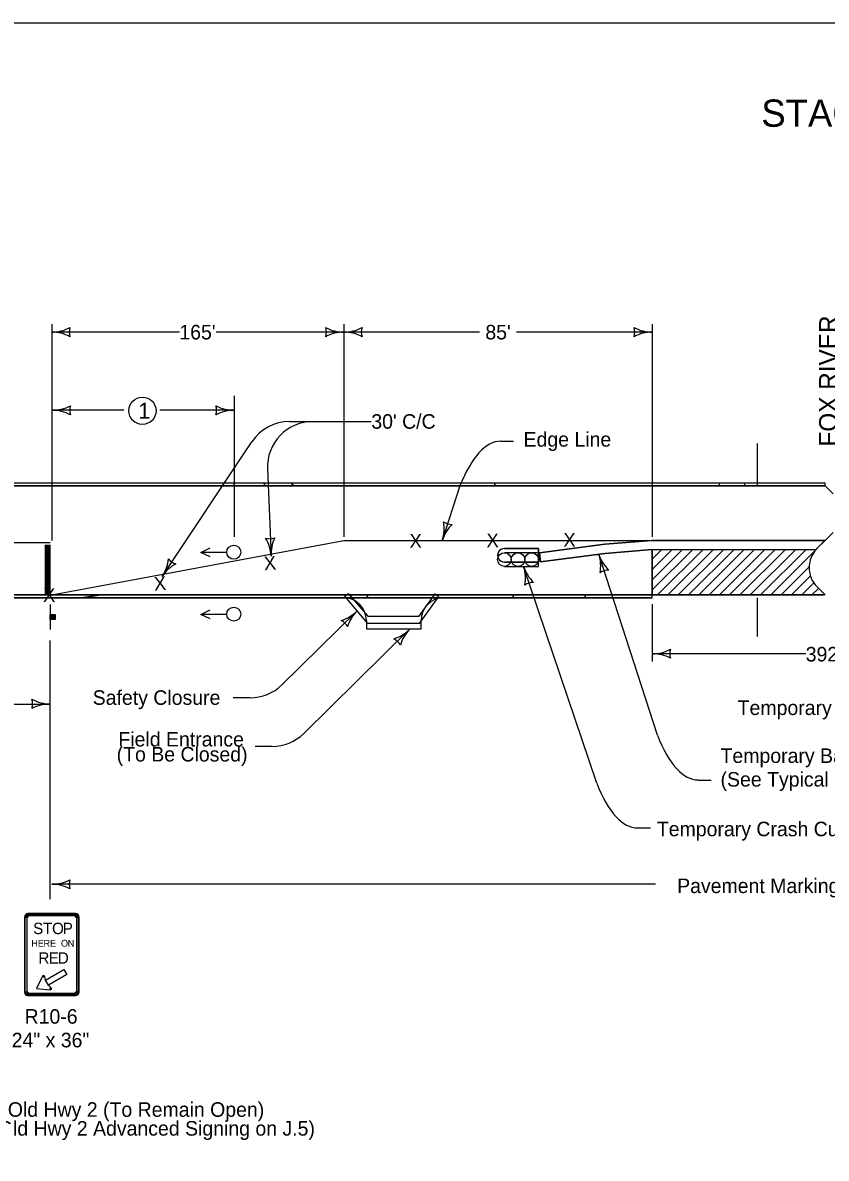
# Model space of a CAD drawing. Extents: x -2134934 to -2119606, y -2139046 to -2137036.
# Drawn here: x -2129562 to -2128679, y -2138285 to -2137036 of the extents above; entities that cross this region are included whole.
import ezdxf

# ---------------------------------------------------------------- set-up
doc = ezdxf.new("R2010")
doc.units = 0
for name, color, linetype in [('Default', 7, 'Continuous'), ('dsnCellElements', 7, 'Continuous'), ('dsnCellsNorthArrow', 7, 'Continuous'), ('dsnStdLabel', 7, 'Continuous'), ('dsnStdLineWork', 7, 'Continuous'), ('dsnStdShading', 7, 'Continuous'), ('Level 2', 7, 'Continuous')]:
    doc.layers.add(name, color=color, linetype=linetype)

msp = doc.modelspace()

# ---------------------------------------------------------------- linework, layer by layer
at = {"layer": 'Default'}
for p, q in [((-2129208, -2137666.4), (-2129204.2, -2137663.4)), ((-2129204.2, -2137663.4), (-2129182.8, -2137688.4)), ((-2129126.3, -2137688.4), (-2129108.6, -2137664.1)), ((-2129108.6, -2137664.1), (-2129105.1, -2137666.7)), ((-2129182.8, -2137696.5), (-2129208, -2137666.4)), ((-2129105.1, -2137666.7), (-2129126.3, -2137696.5)), ((-2129182.8, -2137688.4), (-2129126.3, -2137688.4)), ((-2129126.3, -2137696.5), (-2129182.8, -2137696.5))]:
    msp.add_line(p, q, dxfattribs=at)
msp.add_lwpolyline([(-2130232, -2137035.9), (-2127097, -2137035.9), (-2127097, -2139045.9), (-2130232, -2139045.9)], close=True, dxfattribs=at)
at = {"layer": 'dsnCellElements'}
for centre, radius, start, end in [((-2129530.1, -2137333.7), 42.5, 270, 298.0725), ((-2129530.1, -2137418.7), 42.5, 61.9275, 90), ((-2129494.5, -2137376.2), 16.4, 162.2666, 197.7334), ((-2129244.7, -2137376.2), 16.4, 342.2666, 17.7334), ((-2129209.1, -2137333.7), 42.5, 241.9275, 270), ((-2129209.1, -2137418.7), 42.5, 90, 118.0725), ((-2129209.1, -2137333.7), 42.5, 270, 298.0725), ((-2129209.1, -2137418.7), 42.5, 61.9275, 90), ((-2129173.5, -2137376.2), 16.4, 162.2666, 197.7334), ((-2128905.8, -2137376.2), 16.4, 342.2666, 17.7334), ((-2128870.1, -2137333.7), 42.5, 241.9275, 270), ((-2128870.1, -2137418.7), 42.5, 90, 118.0725), ((-2129141.4, -2137592.1), 42.5, 342.0849, 10.1574), ((-2129060.5, -2137618.2), 42.5, 134.0124, 162.0849), ((-2129090, -2137571.3), 16.4, 234.3516, 269.8183), ((-2129290.8, -2137586.9), 16.4, 255.0909, 290.5576), ((-2129331.5, -2137624.5), 42.5, 2.8243, 30.8968), ((-2129246.6, -2137620.4), 42.5, 154.7518, 182.8243), ((-2129444.2, -2137621.2), 42.5, 326.2987, 354.3712), ((-2129389.1, -2137615.2), 16.4, 218.5654, 254.0321), ((-2128969.3, -2137633.4), 42.5, 349.8426, 17.9151), ((-2128888.4, -2137607.3), 42.5, 197.9151, 225.9876), ((-2129373.5, -2137668.4), 42.5, 118.2263, 146.2987), ((-2129051.9, -2137646.9), 42.5, 349.8426, 17.9151), ((-2128971, -2137620.8), 42.5, 197.9151, 225.9876), ((-2128917.9, -2137654.2), 16.4, 90.1817, 125.6484), ((-2129000.5, -2137667.7), 16.4, 90.1817, 125.6484), ((-2129224.6, -2137652.6), 42.5, 287.1972, 315.2696), ((-2129164.3, -2137712.4), 42.5, 135.2696, 163.3421), ((-2129219.5, -2137707.8), 16.4, 27.5363, 63.003), ((-2129166.7, -2137672.7), 42.5, 287.1972, 315.2696), ((-2129106.3, -2137732.6), 42.5, 135.2696, 163.3421), ((-2129161.6, -2137728), 16.4, 27.5363, 63.003), ((-2129530.1, -2137940.8), 42.5, 270, 298.0725), ((-2129530.1, -2138025.8), 42.5, 61.9275, 90), ((-2129494.5, -2137983.3), 16.4, 162.2666, 197.7334)]:
    msp.add_arc(centre, radius, start, end, dxfattribs=at)
at = {"layer": 'dsnStdLabel'}
for p, q in [((-2129560.1, -2138019.4), (-2129556.4, -2138019.4)), ((-2129559.2, -2138019.4), (-2129557.6, -2138019.4)), ((-2129556.4, -2138019.4), (-2129556.4, -2138015.6)), ((-2129556.4, -2138018.1), (-2129556.4, -2138016.6)), ((-2129503.9, -2138015.6), (-2129503.9, -2138019.4)), ((-2129503.9, -2138016.6), (-2129503.9, -2138018.1)), ((-2129503.9, -2138019.4), (-2129500.1, -2138019.4)), ((-2129502.6, -2138019.4), (-2129501.1, -2138019.4)), ((-2129540.3, -2138084.4), (-2129539.2, -2138085)), ((-2129539.2, -2138085), (-2129537.9, -2138084.7)), ((-2129556.4, -2138101.9), (-2129560.1, -2138101.9)), ((-2129557.6, -2138101.9), (-2129559.2, -2138101.9)), ((-2129556.4, -2138105.6), (-2129556.4, -2138101.9)), ((-2129530.8, -2138097), (-2129531.7, -2138098)), ((-2129531.7, -2138098), (-2129531.7, -2138099.2)), ((-2129500.1, -2138101.9), (-2129503.9, -2138101.9)), ((-2129503.9, -2138101.9), (-2129503.9, -2138105.6)), ((-2129501.1, -2138101.9), (-2129502.6, -2138101.9)), ((-2129556.4, -2138104.7), (-2129556.4, -2138103.1)), ((-2129503.9, -2138103.1), (-2129503.9, -2138104.7))]:
    msp.add_line(p, q, dxfattribs=at)
for points in [[(-2129556.4, -2138105.6), (-2129503.9, -2138105.6), (-2129503.9, -2138101.9), (-2129500.1, -2138101.9), (-2129500.1, -2138019.4), (-2129503.9, -2138019.4), (-2129503.9, -2138015.6), (-2129556.4, -2138015.6), (-2129556.4, -2138019.4), (-2129560.1, -2138019.4), (-2129560.1, -2138101.9), (-2129556.4, -2138101.9), (-2129556.4, -2138105.6)], [(-2129557.6, -2138019.4), (-2129557.6, -2138101.9), (-2129559.2, -2138101.9), (-2129559.2, -2138019.4), (-2129557.6, -2138019.4)], [(-2129503.9, -2138018.1), (-2129556.4, -2138018.1), (-2129556.4, -2138016.6), (-2129503.9, -2138016.6), (-2129503.9, -2138018.1)], [(-2129502.6, -2138101.9), (-2129502.6, -2138019.4), (-2129501.1, -2138019.4), (-2129501.1, -2138101.9), (-2129502.6, -2138101.9)], [(-2129516.7, -2138076.9), (-2129513.5, -2138082.6), (-2129533.8, -2138094.3), (-2129537.1, -2138088.6), (-2129516.7, -2138076.9)], [(-2129546.8, -2138098), (-2129531.7, -2138099.2), (-2129531.7, -2138098), (-2129530.8, -2138097), (-2129533.8, -2138094.3), (-2129537.1, -2138088.6), (-2129537.9, -2138084.7), (-2129539.2, -2138085), (-2129540.3, -2138084.4), (-2129546.8, -2138098)], [(-2129556.4, -2138103.1), (-2129503.9, -2138103.1), (-2129503.9, -2138104.7), (-2129556.4, -2138104.7), (-2129556.4, -2138103.1)]]:
    msp.add_lwpolyline(points, close=True, dxfattribs=at)
for centre, radius, start, end in [((-2129556.4, -2138019.4), 3.75, 90.0002, 179.9998), ((-2129556.4, -2138019.4), 2.81, 90.0002, 179.9998), ((-2129556.4, -2138019.4), 1.25, 90.0002, 179.9998), ((-2129503.9, -2138019.4), 3.75, 0, 90.0002), ((-2129503.9, -2138019.4), 2.81, 0, 90.0002), ((-2129503.9, -2138019.4), 1.25, 0, 90.0002), ((-2129539.2, -2138085), 1.25, 12.6223, 152.2756), ((-2129556.4, -2138101.9), 3.75, 179.9998, 270.0001), ((-2129556.4, -2138101.9), 2.81, 179.9998, 270.0001), ((-2129556.4, -2138101.9), 1.25, 179.9998, 270.0001), ((-2129531.7, -2138098), 1.25, 267.7243, 47.3776), ((-2129503.9, -2138101.9), 3.75, 270.0001, 0.0003), ((-2129503.9, -2138101.9), 2.81, 270.0001, 0.0003), ((-2129503.9, -2138101.9), 1.25, 270.0001, 0.0003)]:
    msp.add_arc(centre, radius, start, end, dxfattribs=at)
at = {"layer": 'dsnStdLineWork'}
for p, q in [((-2128680.1, -2137542.2), (-2130182.6, -2137542.2)), ((-2128680.1, -2137545.2), (-2130182.6, -2137545.2)), ((-2129603.5, -2137545.2), (-2129329.6, -2137545.2)), ((-2129329.6, -2137542.2), (-2129602.5, -2137542.2)), ((-2129329.6, -2137542.2), (-2129329.6, -2137545.2)), ((-2129296.4, -2137542.2), (-2129329.6, -2137542.2)), ((-2129329.6, -2137545.2), (-2129329.6, -2137542.2)), ((-2129329.6, -2137545.2), (-2129296.2, -2137545.2)), ((-2129266.6, -2137542.2), (-2129296.4, -2137542.2)), ((-2129296.4, -2137542.2), (-2129296.2, -2137545.2)), ((-2129296.2, -2137545.2), (-2129296.4, -2137542.2)), ((-2129296.2, -2137545.2), (-2129264.4, -2137545.2)), ((-2129266.6, -2137542.2), (-2129264.4, -2137545.2)), ((-2129043.1, -2137542.2), (-2129266.6, -2137542.2)), ((-2129264.4, -2137545.2), (-2129266.6, -2137542.2)), ((-2129264.4, -2137545.2), (-2129043.1, -2137545.2)), ((-2128796.1, -2137542.2), (-2129043.1, -2137542.2)), ((-2129043.1, -2137542.2), (-2129043.1, -2137545.2)), ((-2129043.1, -2137545.2), (-2129043.1, -2137542.2)), ((-2129043.1, -2137545.2), (-2128797, -2137545.2)), ((-2128797, -2137545.2), (-2128768.2, -2137545.2)), ((-2128769.2, -2137542.2), (-2128796.1, -2137542.2)), ((-2128680.1, -2137542.2), (-2128769.2, -2137542.2)), ((-2128768.2, -2137545.2), (-2128680.1, -2137545.2)), ((-2128680.1, -2137545.2), (-2128680.1, -2137542.2)), ((-2129532, -2137607.7), (-2130184.5, -2137607.7)), ((-2129535.1, -2137665.2), (-2130182.6, -2137665.2)), ((-2130182, -2137665.2), (-2128682, -2137665.2)), ((-2129475.9, -2137665.2), (-2129530.1, -2137665.2)), ((-2129497.6, -2137668.2), (-2129475.9, -2137665.2)), ((-2129475.9, -2137665.2), (-2129497.6, -2137668.2)), ((-2129182.9, -2137665.2), (-2129475.9, -2137665.2)), ((-2129183.9, -2137668.2), (-2129182.9, -2137665.2)), ((-2129182.9, -2137665.2), (-2129183.9, -2137668.2)), ((-2129022.5, -2137665.2), (-2129182.9, -2137665.2)), ((-2129023.4, -2137668.2), (-2129022.5, -2137665.2)), ((-2129022.5, -2137665.2), (-2129023.4, -2137668.2)), ((-2128943.4, -2137665.2), (-2129022.5, -2137665.2)), ((-2128944.3, -2137668.2), (-2128943.4, -2137665.2)), ((-2128943.4, -2137665.2), (-2128944.3, -2137668.2)), ((-2128870.8, -2137665.2), (-2128943.4, -2137665.2)), ((-2128870.1, -2137665.2), (-2128870.8, -2137665.2)), ((-2128870.1, -2137668.2), (-2128870.1, -2137665.2)), ((-2128870.1, -2137668.2), (-2128870.1, -2137665.2)), ((-2130182.6, -2137668.2), (-2129497.6, -2137668.2)), ((-2129497.6, -2137668.2), (-2129183.9, -2137668.2)), ((-2129183.9, -2137668.2), (-2129023.4, -2137668.2)), ((-2129023.4, -2137668.2), (-2128944.3, -2137668.2)), ((-2128944.3, -2137668.2), (-2128870.1, -2137668.2))]:
    msp.add_line(p, q, dxfattribs=at)
for points in [[(-2130182.4, -2137545.2), (-2128872.4, -2137545.2)], [(-2128870.1, -2137665.2), (-2130182.6, -2137665.2)], [(-2129532.1, -2137665.2), (-2129533.1, -2137665.2), (-2129534.1, -2137665.2), (-2129535.1, -2137665.2)], [(-2129530.1, -2137665.2), (-2129531.1, -2137665.2), (-2129532.1, -2137665.2)], [(-2128870.1, -2137668.2), (-2130182.6, -2137668.2)]]:
    msp.add_lwpolyline(points, dxfattribs=at)
for start, end in [(156.382, 168.6701), (156.382, 168.6701), (11.3299, 23.618), (11.3299, 23.618)]:
    msp.add_arc((-2128782.6, -2137548), 14.7, start, end, dxfattribs=at)
at = {"layer": 'dsnStdShading'}
for p, q in [((-2128995.2, -2137614.1), (-2129032.7, -2137614.1)), ((-2128995.2, -2137629.1), (-2128995.2, -2137614.1)), ((-2129032.7, -2137629.1), (-2128995.2, -2137629.1))]:
    msp.add_line(p, q, dxfattribs=at)
msp.add_arc((-2129032.7, -2137621.6), 7.5, 90.0024, 269.9972, dxfattribs=at)
at = {"layer": 'Level 2'}
for p, q in [((-2129530.1, -2137367.6), (-2129530.1, -2137605.2)), ((-2129389.9, -2137376.2), (-2129530.1, -2137376.2)), ((-2129209.1, -2137376.2), (-2129349.4, -2137376.2)), ((-2129209.1, -2137367.6), (-2129209.1, -2137601.1)), ((-2129059.9, -2137376.2), (-2129209.1, -2137376.2)), ((-2128870.1, -2137376.2), (-2129019.4, -2137376.2)), ((-2128870.1, -2137367.6), (-2128870.1, -2137601.1)), ((-2129329.6, -2137446.2), (-2129329.6, -2137601.1)), ((-2129450.8, -2137462.1), (-2129529.6, -2137462.1)), ((-2129329.6, -2137462.1), (-2129411.4, -2137462.1)), ((-2129268.5, -2137474.4), (-2129178.9, -2137474.4)), ((-2129408.8, -2137644.8), (-2129310.1, -2137496.7)), ((-2129036.8, -2137496), (-2129022.6, -2137496)), ((-2128754.7, -2137498.8), (-2128754.7, -2137545.2)), ((-2129293, -2137526.5), (-2129289, -2137622.5)), ((-2128680.1, -2137545.2), (-2130182.6, -2137545.2)), ((-2129081.5, -2137545.2), (-2129100.9, -2137605.2)), ((-2128680.1, -2137545.2), (-2128671.3, -2137553.9)), ((-2128671.3, -2137553.9), (-2128680.1, -2137545.2)), ((-2128671.3, -2137596.4), (-2128688.9, -2137613.9)), ((-2129537, -2137665.2), (-2129537, -2137610.2)), ((-2129536, -2137665.2), (-2129536, -2137610.2)), ((-2129535, -2137665.2), (-2129535, -2137610.2)), ((-2129534, -2137665.2), (-2129534, -2137610.2)), ((-2129533, -2137665.2), (-2129533, -2137610.2)), ((-2129532, -2137665.2), (-2129532, -2137610.2)), ((-2129530.1, -2137665.2), (-2129209.3, -2137605.2)), ((-2129209.3, -2137605.2), (-2128870.7, -2137605.2)), ((-2129032.7, -2137614.1), (-2128995.2, -2137614.1)), ((-2128995.2, -2137614.1), (-2128995.2, -2137629.1)), ((-2128922.2, -2137609.5), (-2128994.2, -2137618.8)), ((-2128994.2, -2137618.8), (-2128922.2, -2137609.5)), ((-2128994.2, -2137618.8), (-2128922.2, -2137609.5)), ((-2128922.4, -2137619.5), (-2128870.3, -2137615.2)), ((-2128870.3, -2137615.2), (-2128922.4, -2137619.5)), ((-2128870.1, -2137615.2), (-2128922.4, -2137619.5)), ((-2128870.7, -2137605.2), (-2128922.2, -2137609.5)), ((-2128922.2, -2137609.5), (-2128870.7, -2137605.2)), ((-2128922.2, -2137609.5), (-2128870.7, -2137605.2)), ((-2128680.1, -2137605.2), (-2128870.7, -2137605.2)), ((-2128870.7, -2137605.2), (-2128680.1, -2137605.2)), ((-2128870.7, -2137605.2), (-2128680.1, -2137605.2)), ((-2128870.3, -2137615.2), (-2128690.1, -2137615.2)), ((-2128870.3, -2137615.2), (-2128690.1, -2137615.2)), ((-2128825.6, -2137615.2), (-2128870.1, -2137659.7)), ((-2128870.1, -2137615.2), (-2128870.1, -2137665.2)), ((-2128836.9, -2137615.2), (-2128870.1, -2137648.4)), ((-2128848.2, -2137615.2), (-2128870.1, -2137637.1)), ((-2128859.5, -2137615.2), (-2128870.1, -2137625.8)), ((-2128870.1, -2137665.2), (-2128870.1, -2137615.2)), ((-2128814.3, -2137615.2), (-2128864.3, -2137665.2)), ((-2128802.9, -2137615.2), (-2128852.9, -2137665.2)), ((-2128791.6, -2137615.2), (-2128841.6, -2137665.2)), ((-2128780.3, -2137615.2), (-2128830.3, -2137665.2)), ((-2128769, -2137615.2), (-2128819, -2137665.2)), ((-2128757.7, -2137615.2), (-2128807.7, -2137665.2)), ((-2128746.4, -2137615.2), (-2128796.4, -2137665.2)), ((-2128735.1, -2137615.2), (-2128785.1, -2137665.2)), ((-2128723.8, -2137615.2), (-2128773.8, -2137665.2)), ((-2128712.4, -2137615.2), (-2128762.4, -2137665.2)), ((-2128701.1, -2137615.2), (-2128751.1, -2137665.2)), ((-2128688.9, -2137613.9), (-2128680.1, -2137605.2)), ((-2129337.9, -2137618.6), (-2129365.8, -2137618.6)), ((-2128995.2, -2137618.8), (-2129032.7, -2137618.8)), ((-2128995.2, -2137633.8), (-2128995.2, -2137618.8)), ((-2128994.2, -2137618.8), (-2128992.9, -2137628.7)), ((-2128992.9, -2137628.7), (-2128994.2, -2137618.8)), ((-2128992.9, -2137628.7), (-2128994.2, -2137618.8)), ((-2128992.9, -2137628.7), (-2128922.4, -2137619.5)), ((-2128922.4, -2137619.5), (-2128992.9, -2137628.7)), ((-2128922.4, -2137619.5), (-2128992.9, -2137628.7)), ((-2128864.5, -2137819.5), (-2128928.9, -2137620.3)), ((-2128691.3, -2137616.6), (-2128739.8, -2137665.2)), ((-2128995.2, -2137629.1), (-2129032.7, -2137629.1)), ((-2129032.7, -2137633.8), (-2128995.2, -2137633.8)), ((-2128931.1, -2137872.3), (-2129011.5, -2137633.8)), ((-2128697.7, -2137634.3), (-2128728.5, -2137665.2)), ((-2128696.3, -2137644.3), (-2128717.2, -2137665.2)), ((-2128692.6, -2137651.9), (-2128705.9, -2137665.2)), ((-2130182.6, -2137665.2), (-2128870.1, -2137665.2)), ((-2128687.3, -2137657.9), (-2128694.6, -2137665.2)), ((-2128688.9, -2137656.4), (-2128680.1, -2137665.2)), ((-2129532, -2137675.7), (-2129532, -2137703.2)), ((-2129099.3, -2137668.2), (-2129209.3, -2137668.2)), ((-2128870.1, -2137675.2), (-2128870.1, -2137738.5)), ((-2128754.7, -2137668.2), (-2128754.7, -2137710.9)), ((-2129531.5, -2137692.1), (-2129531.5, -2137686.5)), ((-2129531.3, -2137686.5), (-2129531.3, -2137692.1)), ((-2129531, -2137692.1), (-2129531, -2137686.5)), ((-2129530.7, -2137686.5), (-2129530.7, -2137692.1)), ((-2129530.5, -2137692.1), (-2129530.5, -2137686.5)), ((-2129530.3, -2137686.5), (-2129530.3, -2137692.1)), ((-2129530, -2137692.1), (-2129530, -2137686.5)), ((-2129529.7, -2137686.5), (-2129529.7, -2137692.1)), ((-2129529.5, -2137692.1), (-2129529.5, -2137686.5)), ((-2129529.2, -2137686.5), (-2129529.2, -2137692.1)), ((-2129528.8, -2137692.1), (-2129528.8, -2137686.5)), ((-2129528.4, -2137686.5), (-2129528.4, -2137692.1)), ((-2129528.1, -2137692.1), (-2129528.1, -2137686.5)), ((-2129527.7, -2137686.5), (-2129527.7, -2137692.1)), ((-2129527.5, -2137692.1), (-2129527.5, -2137686.5)), ((-2129527.2, -2137686.5), (-2129527.2, -2137692.1)), ((-2129526.9, -2137692.1), (-2129526.9, -2137686.5)), ((-2129526.6, -2137686.5), (-2129526.6, -2137692.1)), ((-2129337.9, -2137686.6), (-2129365.8, -2137686.6)), ((-2129277.1, -2137763.9), (-2129194.4, -2137682.5)), ((-2129253, -2137817.4), (-2129136.5, -2137702.6)), ((-2129532, -2137999.5), (-2129532, -2137715.2)), ((-2128701.5, -2137729.8), (-2128870.1, -2137729.8)), ((-2129586.7, -2137785.2), (-2129532, -2137785.2)), ((-2129312.2, -2137778.3), (-2129330.6, -2137778.3)), ((-2129288.1, -2137831.8), (-2129306.6, -2137831.8)), ((-2128819.8, -2137868.7), (-2128805.5, -2137868.7)), ((-2128886.4, -2137921.4), (-2128872.2, -2137921.4)), ((-2128866.5, -2137983.3), (-2129530.1, -2137983.3))]:
    msp.add_line(p, q, dxfattribs=at)
for points in [[(-2128680.1, -2137605.2), (-2128680.1, -2137605.2), (-2128671.3, -2137596.4)], [(-2129356.2, -2137623.4), (-2129366.2, -2137618.4), (-2129356.2, -2137613.4)], [(-2128690.1, -2137615.2), (-2128690.1, -2137615.2)], [(-2128680.1, -2137665.2), (-2128870.1, -2137665.2)], [(-2129356.2, -2137691.5), (-2129366.2, -2137686.5), (-2129356.2, -2137681.5)], [(-2129184.3, -2137693.2), (-2129184.3, -2137702.6), (-2129124.3, -2137702.6), (-2129124.3, -2137693.2)]]:
    msp.add_lwpolyline(points, dxfattribs=at)
msp.add_lwpolyline([(-2129531.9, -2137692.1), (-2129531.9, -2137686.5), (-2129526.2, -2137686.5), (-2129526.2, -2137692.1)], close=True, dxfattribs=at)
for centre, radius in [((-2129430.5, -2137462.6), 15), ((-2129330.1, -2137618.2), 7.74), ((-2129032.7, -2137626.3), 7.5), ((-2129032.7, -2137626.3), 7.5), ((-2129017.7, -2137626.3), 7.5), ((-2129017.7, -2137626.3), 7.5), ((-2129002.7, -2137626.3), 7.5), ((-2129002.7, -2137626.3), 7.5), ((-2129330.1, -2137686.3), 7.74)]:
    msp.add_circle(centre, radius, dxfattribs=at)
for centre, radius, start, end in [((-2129529.6, -2137419.6), 42.5, 270, 298.0725), ((-2129529.6, -2137504.6), 42.5, 61.9275, 90), ((-2129494, -2137462.1), 16.4, 162.2666, 197.7334), ((-2129365.3, -2137462.1), 16.4, 342.2666, 17.7334), ((-2129329.6, -2137419.6), 42.5, 241.9275, 270), ((-2129329.6, -2137504.6), 42.5, 90, 118.0725), ((-2129268.5, -2137524.4), 50, 90, 146.2987), ((-2129243.1, -2137524.4), 50, 90, 182.3873), ((-2129032.7, -2137621.6), 7.5, 89.9996, 270), ((-2128667.7, -2137635.2), 30, 135, 225), ((-2128667.7, -2137635.2), 30, 135, 138.2713), ((-2129209.3, -2137693.2), 25, 0, 90), ((-2129099.3, -2137693.2), 25, 90, 180), ((-2128870.1, -2137687.4), 42.5, 270, 298.0725), ((-2128834.5, -2137729.8), 16.4, 162.2666, 197.7334), ((-2128870.1, -2137772.3), 42.5, 61.9275, 90), ((-2129312.2, -2137728.3), 50, 270, 314.5635), ((-2129567.6, -2137784.5), 16.4, 341.2666, 16.7334), ((-2129532.7, -2137827.7), 42.5, 89.0176, 117.0725), ((-2129531.2, -2137742.7), 42.5, 240.9275, 268.9824), ((-2129288.1, -2137781.8), 50, 270, 314.5635)]:
    msp.add_arc(centre, radius, start, end, dxfattribs=at)
for centre, major_axis, start_param, end_param in [((-2129036.8, -2137709), (0, 212.9), 0, 0.693162), ((-2128819.8, -2137655.7), (0, -212.9), 5.590023, 6.283185), ((-2128886.4, -2137708.5), (0, -212.9), 5.590023, 6.283185)]:
    msp.add_ellipse(centre, major_axis=major_axis, ratio=0.328743, start_param=start_param, end_param=end_param, dxfattribs=at)

# ---------------------------------------------------------------- texts
at = {"layer": 'dsnCellsNorthArrow'}
msp.add_text('FOX RIVER', height=20, rotation=90, dxfattribs=at).set_placement((-2128666.8, -2137502))
at = {"layer": 'dsnStdLabel'}
for s, height, p in [('STAGE 2', 30, (-2128750.3, -2137150.4)), ('S', 12.5, (-2129550.6, -2138038.1)), ('T', 12.5, (-2129539.8, -2138038.1)), ('O', 12.5, (-2129529.8, -2138038.1)), ('P', 12.5, (-2129518.1, -2138038.1)), ('H', 7.5, (-2129552.6, -2138051.9)), ('E', 7.5, (-2129545.5, -2138051.9)), ('R', 7.5, (-2129539.2, -2138051.9)), ('E', 7.5, (-2129532.1, -2138051.9)), ('O', 7.5, (-2129520, -2138051.9)), ('N', 7.5, (-2129512.6, -2138051.9)), ('R', 12.5, (-2129544.8, -2138070.6)), ('E', 12.5, (-2129533.5, -2138070.6)), ('D', 12.5, (-2129523.5, -2138070.6)), ('R10-6', 16, (-2129560, -2138136.6)), ('24" x 36"', 16, (-2129574.2, -2138162.6))]:
    msp.add_text(s, height=height, dxfattribs=at).set_placement(p)
at = {"layer": 'Level 2'}
for s, height, p in [("165'", 16, (-2129389.9, -2137384.2)), ("85'", 16, (-2129053.6, -2137384.2)), ('1', 17.5, (-2129434.9, -2137471.3)), ("30' C/C", 16, (-2129178.9, -2137482.4)), ('Edge Line', 16, (-2129011.6, -2137502.1)), ('X', 15, (-2129136.9, -2137613.3)), ('X', 15, (-2129052.3, -2137612.7)), ('X', 15, (-2128967.8, -2137612.1)), ('X', 15, (-2129539.6, -2137672.8)), ("392.5'", 16, (-2128701.5, -2137738.3)), ('Safety Closure', 16, (-2129485.1, -2137786)), ('Temporary Crash Cushion', 16, (-2128776.3, -2137797.2)), ('Field Entrance ', 16, (-2129456.9, -2137831.8)), ('(To Be Closed)', 16, (-2129458.8, -2137848.3)), ('Temporary Barrier Rail', 16, (-2128795.1, -2137849.9)), ('(See Typical 8212)', 16, (-2128795.1, -2137875.9)), ('Temporary Crash Cushion', 16, (-2128865.1, -2137930.5)), ('Pavement Marking Removal Limits', 16, (-2128842.8, -2137993)), ('Old Hwy 2 (To Remain Open)', 16, (-2129578.4, -2138239)), ('(See Old Hwy 2 Advanced Signing on J.5)', 16, (-2129640.5, -2138259.7))]:
    msp.add_text(s, height=height, dxfattribs=at).set_placement(p)
for p in [(-2129296.5, -2137638), (-2129417.3, -2137660.4)]:
    msp.add_text('X', height=15, rotation=3.5803, dxfattribs=at).set_placement(p)

doc.saveas('drawing.dxf')
